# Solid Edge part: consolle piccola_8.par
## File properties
Last saved by: i.fialdini
Revision: 62
Tipo di contenuto documento: 0
Accuracy: 0.990
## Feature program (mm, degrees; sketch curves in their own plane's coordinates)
body "unnamed Body 1"
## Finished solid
Body 1: solid body, 6 faces, 12 edges, 8 vertices.
  Faces by surface: plane 6
  Edges by curve: line 12
Bounding box of the edges (mm): 362.238 x 30.000 x 2.000, from (-175.738, -924.1568, 700.9818) to (186.5, -894.1568, 702.9818).
Planar faces by outward normal: +x 1, +y 1, +z 1, -x 1, -y 1, -z 1
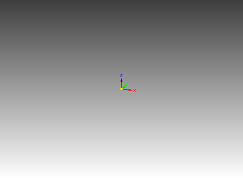
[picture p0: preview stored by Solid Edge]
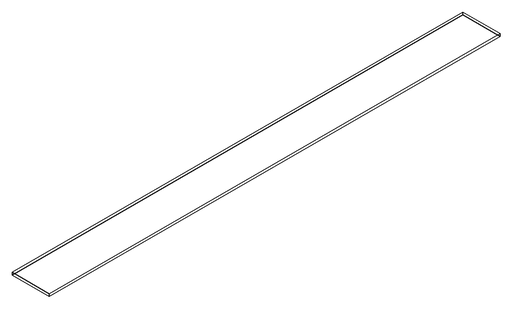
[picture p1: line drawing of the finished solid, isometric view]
